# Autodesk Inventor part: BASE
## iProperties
Author: GJOHNST2
Shininess: 20.0
Length Units: 11272
Angle Units: 11286
Time Units: 11279
Mass Units: 11290
Length Display Precision: 3
Angle Display Precision: 2
Compacted: True
PropertySet Name: _Private Model Information
Created: 2001-11
Part Number: BASE
Material: Stainless Steel, Austenitic
Document SubType Name: Modeling
Designer: GJOHNST2
Control State: 0
Master: False
Checked Out: False
PropertySet Name: Design Tracking Control
Density: 8.03
Volumn: 242.81945017674386
Area: 515.778205637812
PropertySet Name: Model Information
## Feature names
1. Extrusion1
2. Extrusion2
3. Fillet2
4. Fillet3
5. Fillet4
6. Extrusion3
7. Fillet6
8. Extrusion4
9. Extrusion5
10. Fillet9
11. Extrusion6
12. Hole1
13. Fillet10
